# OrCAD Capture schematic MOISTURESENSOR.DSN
size A; title: Moisture Sensor circuit; rev: 1
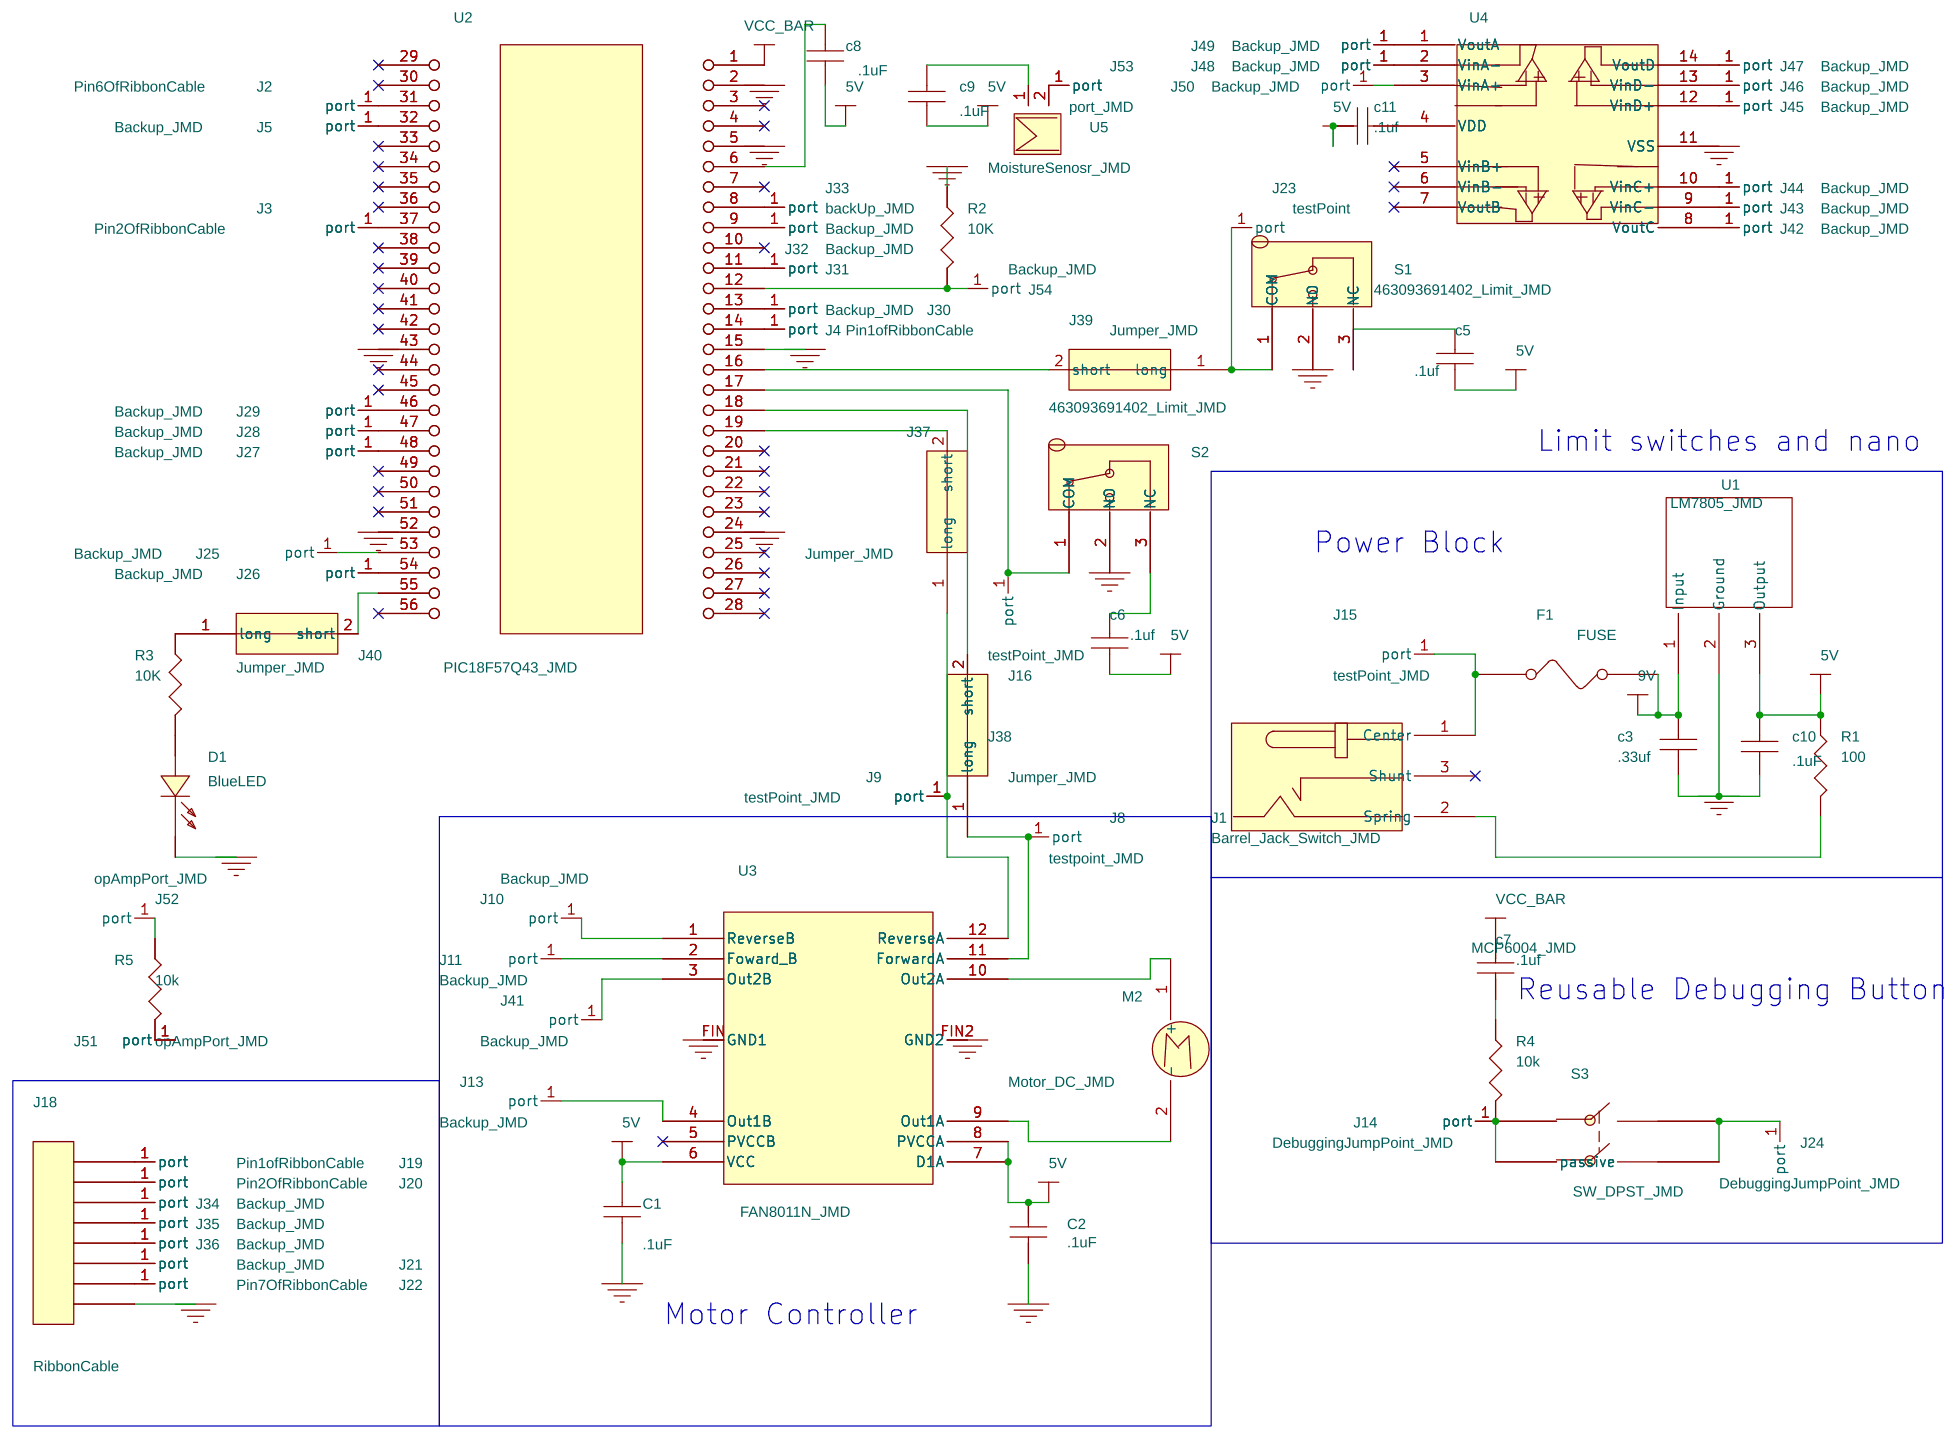
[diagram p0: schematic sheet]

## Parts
C1  .1uF  [capacitor]
C2  .1uF  [capacitor]
c3  .33uf  [capacitor]
c5  .1uf  [capacitor]
c6  .1uf  [capacitor]
c7  .1uf  [capacitor]
c8  .1uF  [capacitor]
c9  .1uF  [capacitor]
c10  .1uF  [capacitor]
c11  .1uf  [capacitor]
D1  BlueLED  [capacitor]
F1  FUSE
J1  Barrel_Jack_Switch_JMD  [BarrelJackdevelopers_JMD]
J2  Pin6OfRibbonCable  [MalePinHole]
J3  Pin2OfRibbonCable  [MalePinHole]
J4  Pin1ofRibbonCable  [MalePinHole]
J5  Backup_JMD  [MalePinHole]
J8  testpoint_JMD  [MalePinHole]
J9  testPoint_JMD  [MalePinHole]
J10  Backup_JMD  [MalePinHole]
J11  Backup_JMD  [MalePinHole]
J13  Backup_JMD  [MalePinHole]
J14  DebuggingJumpPoint_JMD  [MalePinHole]
J15  testPoint_JMD  [MalePinHole]
J16  testPoint_JMD  [MalePinHole]
J18  RibbonCable
J19  Pin1ofRibbonCable  [MalePinHole]
J20  Pin2OfRibbonCable  [MalePinHole]
J21  Backup_JMD  [MalePinHole]
J22  Pin7OfRibbonCable  [MalePinHole]
J23  testPoint  [MalePinHole]
J24  DebuggingJumpPoint_JMD  [MalePinHole]
J25  Backup_JMD  [MalePinHole]
J26  Backup_JMD  [MalePinHole]
J27  Backup_JMD  [MalePinHole]
J28  Backup_JMD  [MalePinHole]
J29  Backup_JMD  [MalePinHole]
J30  Backup_JMD  [MalePinHole]
J31  Backup_JMD  [MalePinHole]
J32  Backup_JMD  [MalePinHole]
J33  backUp_JMD  [MalePinHole]
J34  Backup_JMD  [MalePinHole]
J35  Backup_JMD  [MalePinHole]
J36  Backup_JMD  [MalePinHole]
J37  Jumper_JMD  [capacitor]
J38  Jumper_JMD  [capacitor]
J39  Jumper_JMD  [capacitor]
J40  Jumper_JMD  [capacitor]
J41  Backup_JMD  [MalePinHole]
J42  Backup_JMD  [MalePinHole]
J43  Backup_JMD  [MalePinHole]
J44  Backup_JMD  [MalePinHole]
J45  Backup_JMD  [MalePinHole]
J46  Backup_JMD  [MalePinHole]
J47  Backup_JMD  [MalePinHole]
J48  Backup_JMD  [MalePinHole]
J49  Backup_JMD  [MalePinHole]
J50  Backup_JMD  [MalePinHole]
J51  opAmpPort_JMD  [MalePinHole]
J52  opAmpPort_JMD  [MalePinHole]
J53  port_JMD  [MalePinHole]
J54  Backup_JMD  [MalePinHole]
M2  Motor_DC_JMD  [screwTerminal]
R1  100  [Resistor_intro]
R2  10K  [Resistor_intro]
R3  10K  [Resistor_intro]
R4  10k  [Resistor_intro]
R5  10k  [Resistor_intro]
S1  463093691402_Limit_JMD  [463093691402_limitSwitch_JMD]
S2  463093691402_Limit_JMD  [463093691402_limitSwitch_JMD]
S3  SW_DPST_JMD  [sw_dpst]
U1  LM7805_JMD  [LinearVoltReg]
U2  PIC18F57Q43_JMD  [Microchip_PIC18F57Q43]
U3  FAN8011N_JMD  [hBridgeWithFin]
U4  MCP6004_JMD
U5  MoistureSenosr_JMD  [screwTerminal]

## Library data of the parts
C1 C2 c3 c5-c11 = CAPACITOR_NON-POL
D1 = LED
F1 = FUSE
J1 = Barrel_Jack_Switch_JMD
J2-J5 J8-J11 J14-J16 J19-J36 J43-J46 J48 J50-J54 = MalePinPlaceHolder_JMD
J13 J41 = MalePinPlaceHolder_JMD_0
J18 = CONN_TRBLK_8
J37-J40 = MaleHeaderPin_JMD
J42 = MalePinPlaceHolder_JMD_4
J47 = MalePinPlaceHolder_JMD_3
J49 = MalePinPlaceHolder_JMD_1
M2 = Motor_DC_JMD
R1-R5 = RESISTOR
S1 S2 = 463093691402_Limit_JMD
S3 = SW_DPST_JMD
U1 = LM7805_JMD_0
U2 = PIC18F57Q43_JMD
U3 = FAN8011N_JMD
U4 = MCP6004_JMD
U5 = MoistureSenosr_JMD

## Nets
5v: C1.1 C2.1 c5.2 c6.2 c7.1 c8.1 c9.1 c10.2 c11.1 R1.1 U1.3(Output) U3.6(VCC) U3.7(D1A) U3.8(PVCCA)
9v: c3.1 F1.2 U1.1(Input)
+5V: U2.1(Vbus)
GND: C1.2 C2.2 c3.2 c10.1 R2.1 S1.2(NO) S2.2(NO) U1.2(Ground) U2.5(GND1) U2.15(GND2) U2.24(GND3) U2.52(GND5) U3.FIN(GND1) U3.FIN2(GND2) U4.11(VSS)
GND_POWER: D1.1(CATHODE) J18.8 U2.2(VOFF) U2.43(GND4)
N10172: J1.2(Spring) R1.2
N11688: J8.1(port) J38.1(long) U3.11(ForwardA)
N11692: M2.1(+) U3.10(Out2A)
N11744: M2.2(-) U3.9(Out1A)
N12185: J37.2(short) U2.19(RB5)
N12217: J38.2(short) U2.18(RD5)
N12354: J16.1(port) S2.1(COM) U2.17(RD6)
N12502: c6.1 S2.3(NC)
N12545: J54.1(port) R2.2 U2.12(RA2)
N13111: F1.1 J1.1(Center) J15.1(port)
N13485: c5.1 S1.3(NC)
N13690: c9.2 U5.1
N14820: J13.1(port) U3.4(Out1B)
N14829: J41.1(port) U3.3(Out2B)
N14838: J11.1(port) U3.2(Foward_B)
N14844: J10.1(port) U3.1(ReverseB)
N14994: J14.1(port) R4.2 S3.1(passive) S3.3
N14998: J24.1(port) S3.2 S3.4
N16476: c8.2 U2.6(VTG)
N17924: J23.1(port) J39.1(long) S1.1(COM)
N17960: J9.1(port) J37.1(long) U3.12(ReverseA)
N28673: J39.2(short) U2.16(RD7)
N29488: J40.2(short) U2.55(RF2)
N39935: J25.1(port) U2.53(RF0)
N43236: c7.2 R4.1
N46817: J52.1(port) R5.1
N47148: J51.1(port) R5.2
N47448: J50.1(port) U4.3(VinA+)
N48205: J42.1(port) U4.8(VoutC)
N48207: J44.1(port) U4.10(VinC+)
N48209: J27.1(port) U2.48(RD0)
N48212: J43.1(port) U4.9(VinC-)
N48216: J33.1(port) U2.8(RA6)
N48218: J26.1(port) U2.54(RF1)
N48219: J30.1(port) U2.13(RA1)
N48220: J18.1 J19.1(port)
N48222: J18.5 J36.1(port)
N48223: J31.1(port) U2.11(RB0)
N48225: J49.1(port) U4.1(VoutA)
N48226: J32.1(port) U2.9(RA5)
N48228: J29.1(port) U2.46(RE2)
N48229: J5.1(port) U2.32(RF1U)
N48230: J40.1(long) R3.1
N48231: J53.1(port) U5.2
N48232: c11.2 U4.4(VDD)
N48233: J48.1(port) U4.2(VinA-)
N48234: J18.4 J35.1(port)
N48236: J47.1(port) U4.14(VoutD)
N48237: J18.2 J20.1(port)
N48238: J18.3 J34.1(port)
N48239: J18.6 J21.1(port)
N48240: J2.1(port) U2.31(RF0U)
N48241: J18.7 J22.1(port)
N48242: J4.1(port) U2.14(RA0)
N48243: J46.1(port) U4.13(VinD-)
N48244: J3.1(port) U2.37(RB2)
N48245: J28.1(port) U2.47(RC7)
N48246: D1.2(ANODE) R3.2
N48247: J45.1(port) U4.12(VinD+)

Not connected (* = marked no-connect by the designer): J1 3(Shunt)*; U2 3(RE3)* 4(RB7)* 7(RA7)* 10(RB3)* 20(RF7)* 21(RF6)* 22(RF5)* 23(RF4)* 25(RE1)* 26(RE0)* 27(RC1)* 28(RC0)* 29(NC)* 30(ID)* 33(RB6)* 34(RB4)* 35(RC2)* 36(RC3)* 38(RB1)* 39(RC4)* 40(RC5)* 41(RC6)* 42(RD4)* 44(RA3)* 45(RA4)* 49(RD1)* 50(RD2)* 51(RD3)* 56(RF3)*; U3 5(PVCCB)*; U4 5(VinB+)* 6(VinB-)* 7(VoutB)*

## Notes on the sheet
- Limit switches and nano
- Power Block
- Reusable Debugging Button
- Motor Controller
